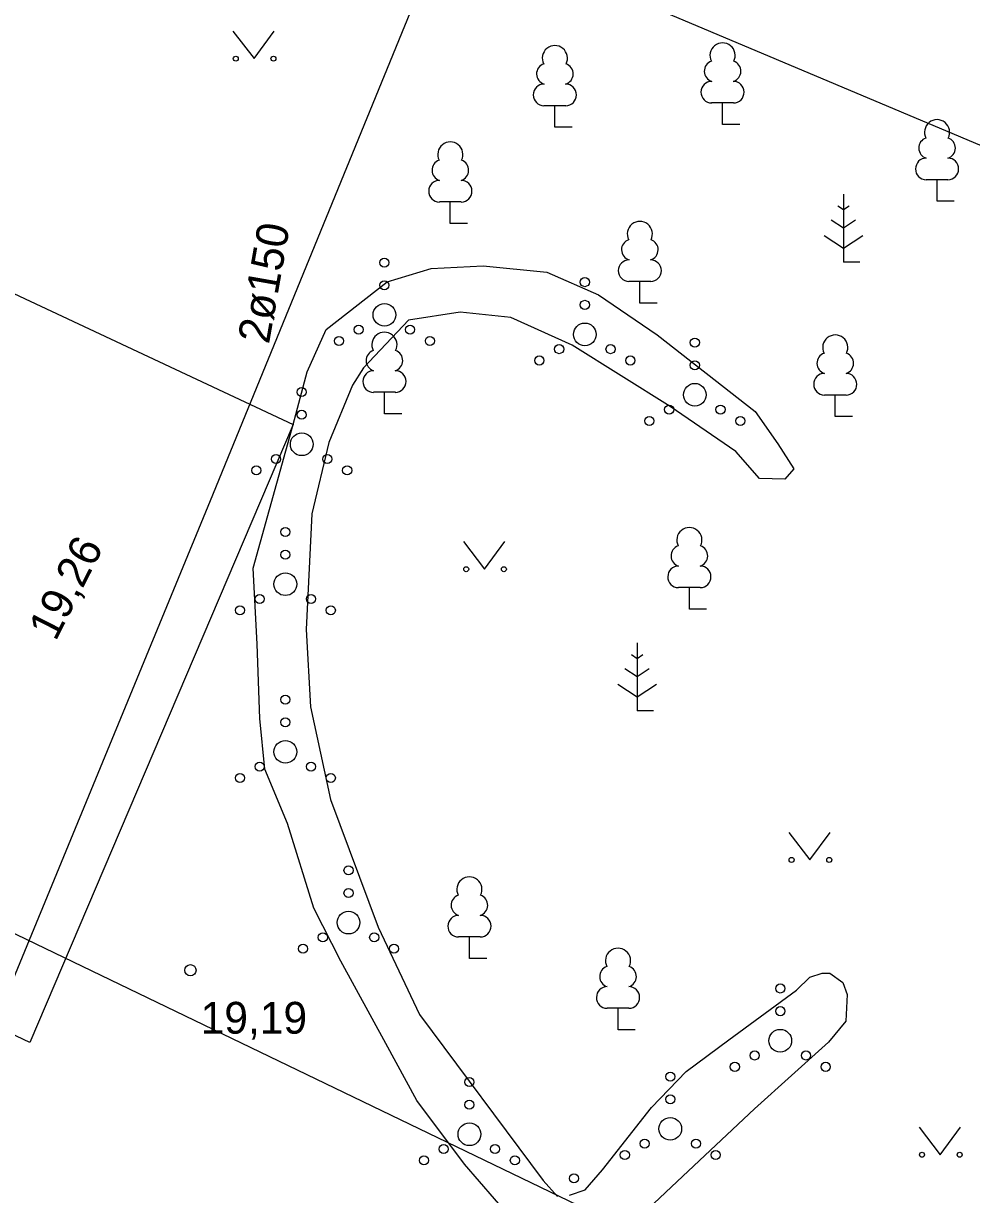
# Model space of a CAD drawing. Extents: x 713497 to 713863, y 6590062 to 6590327.
# Drawn here: x 713754.44 to 713775.3, y 6590210.37 to 6590236.16 of the extents above; entities that cross this region are included whole.
import ezdxf

# ---------------------------------------------------------------- set-up
doc = ezdxf.new("R2010")
doc.units = 0
for name, color, linetype in [('HALJASTUS', 7, 'Continuous'), ('KORGUS', 7, 'Continuous'), ('MPKAABEL', 7, 'Continuous'), ('PUU', 7, 'Continuous'), ('TEE', 7, 'Continuous'), ('TORU NR', 7, 'Continuous'), ('TTRASS', 7, 'Continuous')]:
    doc.layers.add(name, color=color, linetype=linetype)

msp = doc.modelspace()

# ---------------------------------------------------------------- linework, layer by layer
at = {"layer": 'HALJASTUS'}
for p, q in [((713759.047, 6590235.987), (713759.51, 6590235.38)), ((713759.51, 6590235.38), (713759.956, 6590235.987)), ((713764.117, 6590224.747), (713764.58, 6590224.14)), ((713764.58, 6590224.14), (713765.026, 6590224.747)), ((713771.277, 6590218.347), (713771.74, 6590217.74)), ((713771.74, 6590217.74), (713772.186, 6590218.347)), ((713774.147, 6590211.857), (713774.61, 6590211.25)), ((713774.61, 6590211.25), (713775.056, 6590211.857))]:
    msp.add_line(p, q, dxfattribs=at)
for points in [[(713765.13, 6590209.9), (713764.14, 6590211.04), (713763.09, 6590212.44), (713762.41, 6590213.7), (713761.42, 6590215.51), (713760.83, 6590216.68), (713760.25, 6590218.54), (713759.75, 6590219.74), (713759.64, 6590220.85), (713759.58, 6590222.49), (713759.49, 6590224.16), (713760.369, 6590227.324), (713760.68, 6590228.487), (713761.1, 6590229.42), (713762.44, 6590230.47), (713763.41, 6590230.76), (713764.55, 6590230.82), (713765.95, 6590230.68), (713767.09, 6590230.18), (713768.38, 6590229.3), (713770.54, 6590227.61), (713771.04, 6590226.9), (713771.39, 6590226.35), (713771.19, 6590226.12), (713770.63, 6590226.14), (713770.11, 6590226.73), (713768.67, 6590227.72), (713766.51, 6590229.07), (713765.16, 6590229.68), (713764.05, 6590229.8), (713762.91, 6590229.62), (713761.92, 6590228.57), (713761.68, 6590228.19), (713761.16, 6590226.93), (713760.78, 6590225.36), (713760.66, 6590222.81), (713760.75, 6590221.11), (713761.19, 6590219.07), (713762.24, 6590216.26)], [(713762.24, 6590216.26), (713763.15, 6590214.34), (713765.87, 6590210.68), (713766.19, 6590210.33)], [(713766.45, 6590210.36), (713766.8, 6590210.48), (713767.18, 6590210.92), (713768.26, 6590212.29), (713769.02, 6590213.08), (713769.96, 6590213.78), (713771.45, 6590214.87), (713771.74, 6590215.16), (713772.01, 6590215.25), (713772.18, 6590215.25), (713772.47, 6590215.04), (713772.56, 6590214.78), (713772.53, 6590214.19), (713772.15, 6590213.73), (713770.52, 6590212.26), (713768.82, 6590210.66), (713767.15, 6590209.08)]]:
    msp.add_lwpolyline(points, dxfattribs=at)
for centre, radius in [((713759.109, 6590235.38), 0.055), ((713759.938, 6590235.38), 0.055), ((713762.38, 6590230.89), 0.1), ((713766.79, 6590230.46), 0.1), ((713762.38, 6590230.39), 0.1), ((713762.38, 6590229.74), 0.25), ((713766.79, 6590229.96), 0.1), ((713761.815, 6590229.415), 0.1), ((713762.945, 6590229.415), 0.1), ((713766.79, 6590229.31), 0.25), ((713761.38, 6590229.165), 0.1), ((713763.38, 6590229.165), 0.1), ((713769.21, 6590229.13), 0.1), ((713766.225, 6590228.985), 0.1), ((713767.355, 6590228.985), 0.1), ((713765.79, 6590228.735), 0.1), ((713767.79, 6590228.735), 0.1), ((713769.21, 6590228.63), 0.1), ((713769.21, 6590227.98), 0.25), ((713760.56, 6590228.04), 0.1), ((713768.645, 6590227.655), 0.1), ((713769.775, 6590227.655), 0.1), ((713760.56, 6590227.54), 0.1), ((713768.21, 6590227.405), 0.1), ((713770.21, 6590227.405), 0.1), ((713760.56, 6590226.89), 0.25), ((713759.995, 6590226.565), 0.1), ((713761.125, 6590226.565), 0.1), ((713759.56, 6590226.315), 0.1), ((713761.56, 6590226.315), 0.1), ((713760.2, 6590224.96), 0.1), ((713760.2, 6590224.46), 0.1), ((713760.2, 6590223.81), 0.25), ((713764.179, 6590224.14), 0.055), ((713765.008, 6590224.14), 0.055), ((713759.635, 6590223.485), 0.1), ((713760.765, 6590223.485), 0.1), ((713759.2, 6590223.235), 0.1), ((713761.2, 6590223.235), 0.1), ((713760.2, 6590221.27), 0.1), ((713760.2, 6590220.77), 0.1), ((713760.2, 6590220.12), 0.25), ((713759.635, 6590219.795), 0.1), ((713760.765, 6590219.795), 0.1), ((713759.2, 6590219.545), 0.1), ((713761.2, 6590219.545), 0.1), ((713761.59, 6590217.51), 0.1), ((713771.339, 6590217.74), 0.055), ((713772.168, 6590217.74), 0.055), ((713761.59, 6590217.01), 0.1), ((713761.59, 6590216.36), 0.25), ((713761.025, 6590216.035), 0.1), ((713762.155, 6590216.035), 0.1), ((713760.59, 6590215.785), 0.1), ((713762.59, 6590215.785), 0.1), ((713771.09, 6590214.91), 0.1), ((713771.09, 6590214.41), 0.1), ((713771.09, 6590213.76), 0.25), ((713770.525, 6590213.435), 0.1), ((713771.655, 6590213.435), 0.1), ((713770.09, 6590213.185), 0.1), ((713772.09, 6590213.185), 0.1), ((713768.67, 6590212.97), 0.1), ((713764.25, 6590212.85), 0.1), ((713768.67, 6590212.47), 0.1), ((713764.25, 6590212.35), 0.1), ((713764.25, 6590211.7), 0.25), ((713768.67, 6590211.82), 0.25), ((713763.685, 6590211.375), 0.1), ((713764.815, 6590211.375), 0.1), ((713768.105, 6590211.495), 0.1), ((713769.235, 6590211.495), 0.1), ((713763.25, 6590211.125), 0.1), ((713765.25, 6590211.125), 0.1), ((713767.67, 6590211.245), 0.1), ((713769.67, 6590211.245), 0.1), ((713774.209, 6590211.25), 0.055), ((713775.038, 6590211.25), 0.055), ((713766.55, 6590210.73), 0.1)]:
    msp.add_circle(centre, radius, dxfattribs=at)
at = {"layer": 'KORGUS'}
msp.add_circle((713758.11, 6590215.31), 0.125, dxfattribs=at)
at = {"layer": 'MPKAABEL'}
msp.add_lwpolyline([(713794.45, 6590198.59), (713789.58, 6590201), (713767.873, 6590209.538), (713741.326, 6590222.344), (713733.59, 6590226.08)], dxfattribs=at)
at = {"layer": 'PUU'}
for p, q in [((713770.06, 6590234.405), (713769.58, 6590234.405)), ((713769.82, 6590233.93), (713769.82, 6590234.405)), ((713766.37, 6590234.345), (713765.89, 6590234.345)), ((713766.13, 6590233.87), (713766.13, 6590234.345)), ((713766.51, 6590233.87), (713766.13, 6590233.87)), ((713770.2, 6590233.93), (713769.82, 6590233.93)), ((713774.78, 6590232.715), (713774.3, 6590232.715)), ((713774.54, 6590232.24), (713774.54, 6590232.715)), ((713772.48, 6590232.4), (713772.48, 6590230.9)), ((713764.07, 6590232.225), (713763.59, 6590232.225)), ((713763.83, 6590231.75), (713763.83, 6590232.225)), ((713772.48, 6590232.05), (713772.356, 6590232.133)), ((713772.604, 6590232.133), (713772.48, 6590232.05)), ((713774.92, 6590232.24), (713774.54, 6590232.24)), ((713772.48, 6590231.65), (713772.213, 6590231.828)), ((713772.747, 6590231.828), (713772.48, 6590231.65)), ((713764.21, 6590231.75), (713763.83, 6590231.75)), ((713772.056, 6590231.489), (713772.48, 6590231.207)), ((713772.48, 6590231.207), (713772.904, 6590231.489)), ((713772.84, 6590230.9), (713772.48, 6590230.9)), ((713768.24, 6590230.475), (713767.76, 6590230.475)), ((713768, 6590230), (713768, 6590230.475)), ((713768.38, 6590230), (713768, 6590230)), ((713762.62, 6590228.035), (713762.14, 6590228.035)), ((713762.38, 6590227.56), (713762.38, 6590228.035)), ((713772.54, 6590227.975), (713772.06, 6590227.975)), ((713772.3, 6590227.5), (713772.3, 6590227.975)), ((713762.76, 6590227.56), (713762.38, 6590227.56)), ((713772.68, 6590227.5), (713772.3, 6590227.5)), ((713769.33, 6590223.735), (713768.85, 6590223.735)), ((713769.09, 6590223.26), (713769.09, 6590223.735)), ((713769.47, 6590223.26), (713769.09, 6590223.26)), ((713767.94, 6590222.52), (713767.94, 6590221.02)), ((713767.94, 6590222.17), (713767.816, 6590222.253)), ((713768.064, 6590222.253), (713767.94, 6590222.17)), ((713767.94, 6590221.77), (713767.673, 6590221.948)), ((713768.207, 6590221.948), (713767.94, 6590221.77)), ((713767.516, 6590221.609), (713767.94, 6590221.327)), ((713767.94, 6590221.327), (713768.364, 6590221.609)), ((713768.3, 6590221.02), (713767.94, 6590221.02)), ((713764.49, 6590216.045), (713764.01, 6590216.045)), ((713764.25, 6590215.57), (713764.25, 6590216.045)), ((713764.63, 6590215.57), (713764.25, 6590215.57)), ((713767.76, 6590214.475), (713767.28, 6590214.475)), ((713767.52, 6590214), (713767.52, 6590214.475)), ((713767.9, 6590214), (713767.52, 6590214))]:
    msp.add_line(p, q, dxfattribs=at)
for centre, radius, start, end in [((713766.13, 6590235.39), 0.277, 332.5799, 207.4201), ((713769.82, 6590235.45), 0.277, 332.5799, 207.4201), ((713765.96, 6590235.043), 0.233, 109.0217, 253.1415), ((713766.3, 6590235.043), 0.233, 286.8508, 70.9859), ((713769.65, 6590235.103), 0.233, 109.0217, 253.1415), ((713769.99, 6590235.103), 0.233, 286.8508, 70.9859), ((713765.893, 6590234.582), 0.238, 90.0016, 269.3953), ((713766.367, 6590234.582), 0.238, 270.6047, 89.9984), ((713769.583, 6590234.642), 0.238, 90.0016, 269.3953), ((713770.057, 6590234.642), 0.238, 270.6047, 89.9984), ((713774.54, 6590233.76), 0.277, 332.5799, 207.4201), ((713774.37, 6590233.413), 0.233, 109.0217, 253.1415), ((713774.71, 6590233.413), 0.233, 286.8508, 70.9859), ((713763.83, 6590233.27), 0.277, 332.5799, 207.4201), ((713763.66, 6590232.923), 0.233, 109.0217, 253.1415), ((713764, 6590232.923), 0.233, 286.8508, 70.9859), ((713774.303, 6590232.952), 0.238, 90.0016, 269.3953), ((713774.777, 6590232.952), 0.238, 270.6047, 89.9984), ((713763.593, 6590232.462), 0.238, 90.0016, 269.3953), ((713764.067, 6590232.462), 0.238, 270.6047, 89.9984), ((713768, 6590231.52), 0.277, 332.5799, 207.4201), ((713767.83, 6590231.173), 0.233, 109.0217, 253.1415), ((713768.17, 6590231.173), 0.233, 286.8508, 70.9859), ((713767.763, 6590230.712), 0.238, 90.0016, 269.3953), ((713768.237, 6590230.712), 0.238, 270.6047, 89.9984), ((713762.38, 6590229.08), 0.277, 332.5799, 207.4201), ((713772.3, 6590229.02), 0.277, 332.5799, 207.4201), ((713762.21, 6590228.733), 0.233, 109.0217, 253.1415), ((713762.55, 6590228.733), 0.233, 286.8508, 70.9859), ((713772.13, 6590228.673), 0.233, 109.0217, 253.1415), ((713772.47, 6590228.673), 0.233, 286.8508, 70.9859), ((713762.143, 6590228.272), 0.238, 90.0016, 269.3953), ((713762.617, 6590228.272), 0.238, 270.6047, 89.9984), ((713772.063, 6590228.212), 0.238, 90.0016, 269.3953), ((713772.537, 6590228.212), 0.238, 270.6047, 89.9984), ((713769.09, 6590224.78), 0.277, 332.5799, 207.4201), ((713768.92, 6590224.433), 0.233, 109.0217, 253.1415), ((713769.26, 6590224.433), 0.233, 286.8508, 70.9859), ((713768.853, 6590223.972), 0.238, 90.0016, 269.3953), ((713769.327, 6590223.972), 0.238, 270.6047, 89.9984), ((713764.25, 6590217.09), 0.277, 332.5799, 207.4201), ((713764.08, 6590216.743), 0.233, 109.0217, 253.1415), ((713764.42, 6590216.743), 0.233, 286.8508, 70.9859), ((713764.013, 6590216.282), 0.238, 90.0016, 269.3953), ((713764.487, 6590216.282), 0.238, 270.6047, 89.9984), ((713767.52, 6590215.52), 0.277, 332.5799, 207.4201), ((713767.35, 6590215.173), 0.233, 109.0217, 253.1415), ((713767.69, 6590215.173), 0.233, 286.8508, 70.9859), ((713767.283, 6590214.712), 0.238, 90.0016, 269.3953), ((713767.757, 6590214.712), 0.238, 270.6047, 89.9984)]:
    msp.add_arc(centre, radius, start, end, dxfattribs=at)
at = {"layer": 'TEE'}
msp.add_lwpolyline([(713863.358, 6590196.431), (713764.059, 6590238.297), (713742.86, 6590246.85), (713734.952, 6590249.165), (713734.699, 6590248.565), (713734.18, 6590247.457), (713733.715, 6590246.43), (713733.203, 6590245.297), (713732.677, 6590244.133), (713734.573, 6590241.161), (713736.147, 6590238.694), (713748.431, 6590232.928), (713760.369, 6590227.324), (713754.579, 6590213.72), (713745.812, 6590217.88), (713744.782, 6590218.369), (713743.276, 6590218.882), (713741.882, 6590218.856), (713740.847, 6590218.526), (713739.892, 6590217.92), (713738.92, 6590215.76), (713731.142, 6590198.62)], dxfattribs=at)
at = {"layer": 'TTRASS'}
msp.add_lwpolyline([(713715.14, 6590205.42), (713715.96, 6590207.06), (713723.64, 6590202.93), (713744.47, 6590191.47), (713758.55, 6590225.65), (713765.83, 6590243.44), (713771.25, 6590261.26), (713780.18, 6590296.56)], dxfattribs=at)

# ---------------------------------------------------------------- texts
at = {"layer": 'KORGUS'}
msp.add_text('19,26', height=0.7, rotation=62.9948, dxfattribs=at).set_placement((713755.143, 6590222.536))
msp.add_text('19,19', height=0.7, dxfattribs=at).set_placement((713758.336, 6590213.915))
at = {"layer": 'TORU NR'}
msp.add_text('2ø150', height=0.7, rotation=79.9901, dxfattribs=at).set_placement((713759.838, 6590229.08))

doc.saveas('drawing.dxf')
